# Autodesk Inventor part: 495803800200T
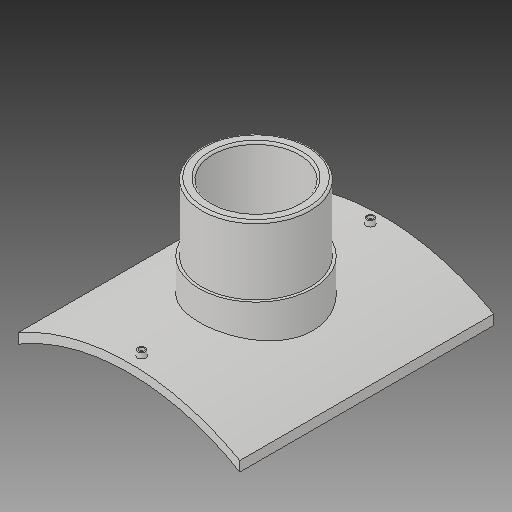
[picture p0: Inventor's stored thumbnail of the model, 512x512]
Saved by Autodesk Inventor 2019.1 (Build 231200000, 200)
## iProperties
Created: 2017-10
Part Number: 495803800200T
Material: Generic
Description: PLASSON BRANCH SADDLE  800x200
Document SubType Name: Modeling
Designer: KIM
Mass: 2754.05 g
Surface Area: 3037.44 cm^2
Volume: 2754.05 cm^3
Density: 1 g/cm^3
Appearance: Default
Author: KIM
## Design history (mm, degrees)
derived "495803.ipt"
feature "Solid1::495803.ipt"
tag "TaggingFeature1"
body "Solid1"
other parameters: "d1" = 16, "d4" = 0, "d12" = 425.6, "d13" = 14, "d14" = 211.5, "d16" = 5 deg, "d18" = 4, "d19" = 14, "d20" = 0, "d21" = 3, "d22" = 0, "d23" = 596, "d25" = 16, "d28" = 0, "d29" = 9.6, "d31" = 0, "d33" = 0, "d34" = 8, "d37" = 126, "d38" = 0, "d39" = 4, "x_" = 16, "D_" = 16
